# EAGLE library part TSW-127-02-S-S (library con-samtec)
THROUGH-HOLE .025" SQ POST HEADER Source: Samtec TSW.pdf
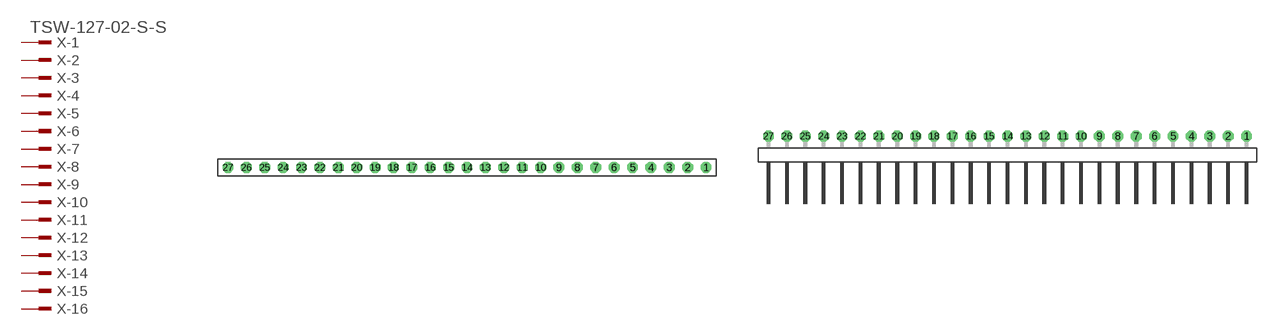
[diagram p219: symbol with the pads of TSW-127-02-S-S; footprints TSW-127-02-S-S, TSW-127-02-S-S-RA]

Designator prefix X; gates -1=MPINV -2=MPIN -3=MPIN -4=MPIN -5=MPIN -6=MPIN -7=MPIN -8=MPIN -9=MPIN -10=MPIN -11=MPIN -12=MPIN -13=MPIN -14=MPIN -15=MPIN -16=MPIN -17=MPIN -18=MPIN -19=MPIN -20=MPIN -21=MPIN -22=MPIN -23=MPIN -24=MPIN -25=MPIN -26=MPIN -27=MPIN

## TSW-127-02-S-S (OC_FARNELL: unknown; OC_NEWARK: unknown)  [TSW-127-02-S-S]
1  -1:1  pas
2  -2:1  pas
3  -3:1  pas
4  -4:1  pas
5  -5:1  pas
6  -6:1  pas
7  -7:1  pas
8  -8:1  pas
9  -9:1  pas
10  -10:1  pas
11  -11:1  pas
12  -12:1  pas
13  -13:1  pas
14  -14:1  pas
15  -15:1  pas
16  -16:1  pas
17  -17:1  pas
18  -18:1  pas
19  -19:1  pas
20  -20:1  pas
21  -21:1  pas
22  -22:1  pas
23  -23:1  pas
24  -24:1  pas
25  -25:1  pas
26  -26:1  pas
27  -27:1  pas

## TSW-127-02-S-S-RA (OC_FARNELL: unknown; OC_NEWARK: unknown)  [TSW-127-02-S-S-RA]
Pads as for TSW-127-02-S-S

## Footprint TSW-127-02-S-S (pad centres in mm)
THROUGH-HOLE .025" SQ POST HEADER Source: Samtec TSW.pdf
drill 1 pad 1.5 octagon: 1 33.02,0; 2 30.48,0; 3 27.94,0; 4 25.4,0; 5 22.86,0; 6 20.32,0; 7 17.78,0; 8 15.24,0; 9 12.7,0; 10 10.16,0; 11 7.62,0; 12 5.08,0; 13 2.54,0; 14 0,0; 15 -2.54,0; 16 -5.08,0; 17 -7.62,0; 18 -10.16,0; 19 -12.7,0; 20 -15.24,0; 21 -17.78,0; 22 -20.32,0; 23 -22.86,0; 24 -25.4,0; 25 -27.94,0; 26 -30.48,0; 27 -33.02,0

## Footprint TSW-127-02-S-S-RA (pad centres in mm)
THROUGH-HOLE .025" SQ POST HEADER Source: Samtec TSW.pdf
drill 1 pad 1.5 octagon: 1 33.02,1.524; 2 30.48,1.524; 3 27.94,1.524; 4 25.4,1.524; 5 22.86,1.524; 6 20.32,1.524; 7 17.78,1.524; 8 15.24,1.524; 9 12.7,1.524; 10 10.16,1.524; 11 7.62,1.524; 12 5.08,1.524; 13 2.54,1.524; 14 0,1.524; 15 -2.54,1.524; 16 -5.08,1.524; 17 -7.62,1.524; 18 -10.16,1.524; 19 -12.7,1.524; 20 -15.24,1.524; 21 -17.78,1.524; 22 -20.32,1.524; 23 -22.86,1.524; 24 -25.4,1.524; 25 -27.94,1.524; 26 -30.48,1.524; 27 -33.02,1.524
